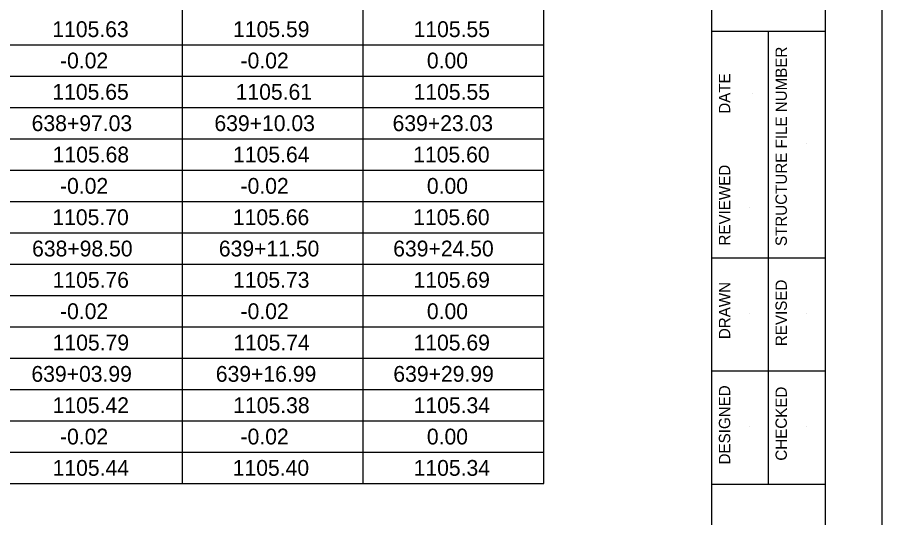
# Model space of a CAD drawing. Extents: x 7.2 to 41.2, y -3.5 to 18.5.
# Drawn here: x 33.53 to 41.16, y 10.19 to 14.61 of the extents above; entities that cross this region are included whole.
import ezdxf

# ---------------------------------------------------------------- set-up
doc = ezdxf.new("R2010")
doc.units = 0
for name, color, linetype in [('BR_P_Gen_Text', 7, 'Continuous'), ('SH_Border', 7, 'Continuous'), ('SH_Cut_Line', 7, 'Continuous'), ('SH_Data', 7, 'Continuous')]:
    doc.layers.add(name, color=color, linetype=linetype)

msp = doc.modelspace()

# ---------------------------------------------------------------- linework, layer by layer
at = {"layer": 'BR_P_Gen_Text'}
for p, q in [((34.99, 10.4892), (34.99, 16.0233)), ((36.5838, 10.4892), (36.5838, 16.0233)), ((38.1776, 10.4892), (38.1776, 16.0233)), ((12.57, 14.3631), (38.1776, 14.3631)), ((12.57, 14.0864), (38.1776, 14.0864)), ((10.6457, 13.8097), (38.1776, 13.8097)), ((12.57, 13.5329), (38.1776, 13.5329)), ((12.57, 13.2562), (38.1776, 13.2562)), ((12.57, 12.9795), (38.1776, 12.9795)), ((10.6457, 12.7028), (38.1776, 12.7028)), ((12.57, 12.4261), (38.1776, 12.4261)), ((12.57, 12.1494), (38.1776, 12.1494)), ((12.57, 11.8727), (38.1776, 11.8727)), ((10.6457, 11.596), (38.1776, 11.596)), ((12.57, 11.3193), (38.1776, 11.3193)), ((12.57, 11.0426), (38.1776, 11.0426)), ((12.57, 10.7659), (38.1776, 10.7659)), ((10.6457, 10.4892), (38.1776, 10.4892))]:
    msp.add_line(p, q, dxfattribs=at)
at = {"layer": 'SH_Border'}
for p, q in [((39.6617, -3.0167), (39.6617, 17.9833)), ((39.6617, 14.4833), (40.6617, 14.4833)), ((40.1617, 10.4833), (40.1617, 14.4833)), ((39.6617, 12.4833), (40.6617, 12.4833)), ((39.6617, 11.4833), (40.6617, 11.4833)), ((39.6617, 10.4833), (40.6617, 10.4833))]:
    msp.add_line(p, q, dxfattribs=at)
msp.add_lwpolyline([(9.1617, 17.9833), (40.6617, 17.9833), (40.6617, -3.0167), (9.1617, -3.0167)], close=True, dxfattribs=at)
at = {"layer": 'SH_Cut_Line'}
msp.add_lwpolyline([(7.1617, 18.4833), (41.1617, 18.4833), (41.1617, -3.5167), (7.1617, -3.5167)], close=True, dxfattribs=at)
at = {"layer": 'SH_Data'}
for p, q in [((40.0213, 13.9326), (40.0213, 13.9326)), ((40.495, 13.4923), (40.495, 13.4923)), ((39.995, 12.9307), (39.995, 12.9307)), ((39.995, 11.9932), (39.995, 11.9932)), ((40.495, 11.9932), (40.495, 11.9932)), ((39.995, 10.9932), (39.995, 10.9932)), ((40.495, 10.9922), (40.495, 10.9922))]:
    msp.add_line(p, q, dxfattribs=at)

# ---------------------------------------------------------------- texts
at = {"layer": 'BR_P_Gen_Text'}
for s, p in [('1105.63', (33.8395, 14.4317)), ('1105.59', (35.4355, 14.4317)), ('1105.55', (37.0287, 14.4317)), ('-0.02', (33.9075, 14.1549)), ('-0.02', (35.5013, 14.1549)), ('0.00', (37.1462, 14.1549)), ('1105.65', (33.84, 13.8782)), ('1105.61', (35.4581, 13.8782)), ('1105.55', (37.0287, 13.8782)), ('638+97.03', (33.6571, 13.6015)), ('639+10.03', (35.2707, 13.6015)), ('639+23.03', (36.8436, 13.6015)), ('1105.68', (33.8428, 13.3248)), ('1105.64', (35.4355, 13.3248)), ('1105.60', (37.0254, 13.3248)), ('-0.02', (33.9075, 13.0481)), ('-0.02', (35.5013, 13.0481)), ('0.00', (37.1462, 13.0481)), ('1105.70', (33.84, 12.7714)), ('1105.66', (35.4333, 12.7714)), ('1105.60', (37.0254, 12.7714)), ('638+98.50', (33.6609, 12.4947)), ('639+11.50', (35.3097, 12.4947)), ('639+24.50', (36.8491, 12.4947)), ('1105.76', (33.8417, 12.218)), ('1105.73', (35.4355, 12.218)), ('1105.69', (37.0282, 12.218)), ('-0.02', (33.9075, 11.9413)), ('-0.02', (35.5013, 11.9413)), ('0.00', (37.1462, 11.9413)), ('1105.79', (33.8428, 11.6646)), ('1105.74', (35.4377, 11.6646)), ('1105.69', (37.0282, 11.6646)), ('639+03.99', (33.6549, 11.3879)), ('639+16.99', (35.2828, 11.3879)), ('639+29.99', (36.8502, 11.3879)), ('1105.42', (33.8417, 11.1112)), ('1105.38', (35.4366, 11.1112)), ('1105.34', (37.0293, 11.1112)), ('-0.02', (33.9075, 10.8345)), ('-0.02', (35.5013, 10.8345)), ('0.00', (37.1462, 10.8345)), ('1105.44', (33.8422, 10.5578)), ('1105.40', (35.4322, 10.5578)), ('1105.34', (37.0293, 10.5578))]:
    msp.add_text(s, height=0.13952, dxfattribs=at).set_placement(p)
at = {"layer": 'SH_Data'}
for s, p in [('STRUCTURE FILE NUMBER', (40.3242, 12.5865)), ('DATE', (39.8242, 13.7548)), ('REVIEWED', (39.8242, 12.5909)), ('DRAWN', (39.8242, 11.7644)), ('REVISED', (40.3242, 11.703)), ('DESIGNED', (39.8242, 10.6582)), ('CHECKED', (40.3242, 10.6912))]:
    msp.add_text(s, height=0.1, rotation=90, dxfattribs=at).set_placement(p)

doc.saveas('drawing.dxf')
